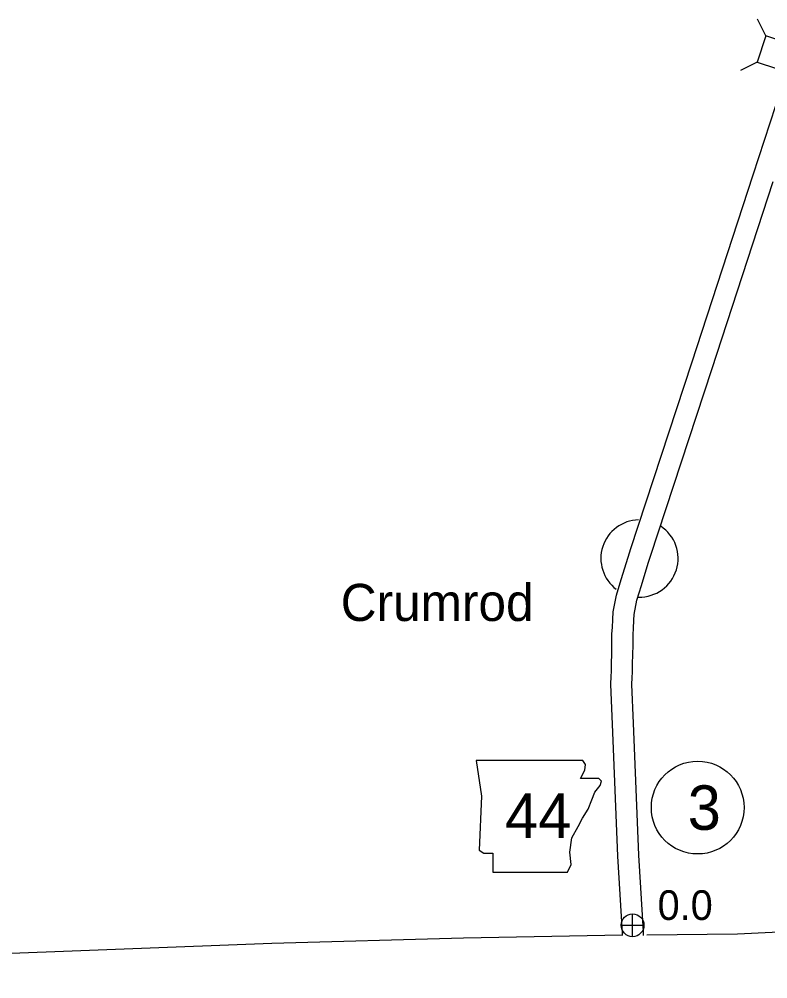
# Model space of a CAD drawing. Extents: x -939622 to -934222, y 1383701 to 1385301.
# Drawn here: x -935886.1 to -935854.11, y 1383823 to 1383863.98 of the extents above; entities that cross this region are included whole.
import ezdxf

# ---------------------------------------------------------------- set-up
doc = ezdxf.new("R2010")
doc.units = 0
for name, color, linetype in [('Level 10', 7, 'Continuous'), ('Level 2', 7, 'Continuous'), ('Level 20', 7, 'Continuous'), ('Level 21', 7, 'Continuous'), ('Level 24', 7, 'Continuous'), ('Level 25', 7, 'Continuous'), ('Level 26', 7, 'Continuous'), ('Level 27', 7, 'Continuous')]:
    doc.layers.add(name, color=color, linetype=linetype)

msp = doc.modelspace()

# ---------------------------------------------------------------- linework, layer by layer
at = {"layer": 'Level 10'}
for points in [[(-935860.082, 1383841.009), (-935859.972, 1383841.37), (-935857.362, 1383849.3), (-935854.737, 1383857.332), (-935852.798, 1383863.263)], [(-935859.221, 1383840.747), (-935859.114, 1383841.098), (-935856.507, 1383849.02), (-935853.882, 1383857.053)], [(-935860.326, 1383824.967), (-935860.526, 1383828.241), (-935860.751, 1383833.878), (-935860.824, 1383835.563), (-935860.808, 1383835.922), (-935860.79, 1383836.123), (-935860.793, 1383836.368), (-935860.784, 1383836.975), (-935860.771, 1383837.186), (-935860.77, 1383837.737), (-935860.746, 1383838.003), (-935860.741, 1383838.348), (-935860.722, 1383838.675), (-935860.582, 1383839.387), (-935860.373, 1383840.055), (-935860.083, 1383841.006)], [(-935859.427, 1383825.022), (-935859.627, 1383828.286), (-935859.852, 1383833.916), (-935859.923, 1383835.562), (-935859.91, 1383835.861), (-935859.889, 1383836.088), (-935859.893, 1383836.367), (-935859.884, 1383836.94), (-935859.871, 1383837.157), (-935859.87, 1383837.696), (-935859.846, 1383837.956), (-935859.841, 1383838.316), (-935859.827, 1383838.562), (-935859.708, 1383839.166), (-935859.513, 1383839.789), (-935859.222, 1383840.744)], [(-935859.42, 1383824.853), (-935859.427, 1383825.015)], [(-935860.321, 1383824.854), (-935860.326, 1383824.974)]]:
    msp.add_lwpolyline(points, dxfattribs=at)
at = {"layer": 'Level 2'}
for points in [[(-935859.277, 1383824.882), (-935855.409, 1383824.915), (-935846.819, 1383825.337)], [(-935913.934, 1383822.998), (-935903.106, 1383823.536), (-935894.989, 1383823.764), (-935875.309, 1383824.525), (-935867.115, 1383824.747)], [(-935867.115, 1383824.747), (-935860.324, 1383824.871)]]:
    msp.add_lwpolyline(points, dxfattribs=at)
at = {"layer": 'Level 20'}
for p, q in [((-935854.195, 1383863.274), (-935854.552, 1383863.981)), ((-935854.566, 1383862.146), (-935855.273, 1383861.789))]:
    msp.add_line(p, q, dxfattribs=at)
msp.add_lwpolyline([(-935854.566, 1383862.146), (-935851.181, 1383861.032), (-935850.809, 1383862.16), (-935854.195, 1383863.274)], close=True, dxfattribs=at)
at = {"layer": 'Level 21'}
msp.add_lwpolyline([(-935866.579, 1383832.321), (-935866.35, 1383830.799), (-935866.452, 1383828.489), (-935866.249, 1383828.362), (-935865.868, 1383828.362), (-935865.868, 1383827.55), (-935862.671, 1383827.55), (-935862.518, 1383827.88), (-935862.569, 1383828.413), (-935862.493, 1383829.022), (-935862.214, 1383829.504), (-935862.036, 1383829.86), (-935861.782, 1383830.24), (-935861.63, 1383830.646), (-935861.503, 1383830.976), (-935861.275, 1383831.255), (-935861.224, 1383831.433), (-935861.326, 1383831.56), (-935862.112, 1383831.56), (-935861.935, 1383831.915), (-935861.909, 1383832.144), (-935862.015, 1383832.319)], close=True, dxfattribs=at)
at = {"layer": 'Level 24'}
for start, end in [(91.3322, 232.9975), (268.6831, 56.6737)]:
    msp.add_arc((-935859.595, 1383840.951), 1.65, start, end, dxfattribs=at)
at = {"layer": 'Level 26'}
for p, q in [((-935859.89, 1383824.798), (-935859.89, 1383825.773)), ((-935860.378, 1383825.285), (-935859.403, 1383825.285))]:
    msp.add_line(p, q, dxfattribs=at)
msp.add_circle((-935859.89, 1383825.285), 0.487, dxfattribs=at)
at = {"layer": 'Level 27'}
msp.add_circle((-935857.109, 1383830.311), 1.98, dxfattribs=at)

# ---------------------------------------------------------------- texts
at = {"layer": 'Level 21'}
msp.add_text('44', height=1.9008, dxfattribs=at).set_placement((-935865.338, 1383829.019))
at = {"layer": 'Level 24'}
msp.add_text('Crumrod', height=1.584, dxfattribs=at).set_placement((-935872.359, 1383838.28))
at = {"layer": 'Level 25'}
msp.add_text('0.0', height=1.2672, dxfattribs=at).set_placement((-935858.821, 1383825.512))
at = {"layer": 'Level 27'}
msp.add_text('3', height=1.901, dxfattribs=at).set_placement((-935857.534, 1383829.36))

doc.saveas('drawing.dxf')
